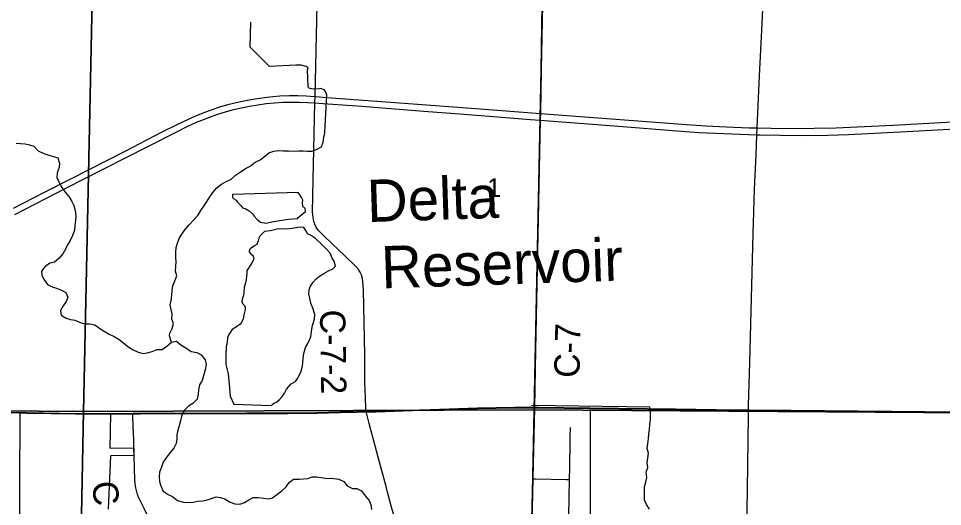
# Model space of a CAD drawing. Extents: x 0 to 42, y 0 to 22.
# Drawn here: x 5.107 to 7.178, y 18.271 to 19.367 of the extents above; entities that cross this region are included whole.
import ezdxf

# ---------------------------------------------------------------- set-up
doc = ezdxf.new("R2010")
doc.units = 0
for name, color, linetype in [('GM_X_City_Street', 7, 'Continuous'), ('GM_X_Corporation', 7, 'Continuous'), ('GM_X_County_Road', 7, 'Continuous'), ('GM_X_County_Road_Text', 7, 'Continuous'), ('GM_X_Interchange_Ramps', 7, 'Continuous'), ('GM_X_Interstate_Route', 7, 'Continuous'), ('GM_X_Minor_Lake', 7, 'Continuous'), ('GM_X_Minor_Lake_Text', 7, 'Continuous'), ('GM_X_Minor_River', 7, 'Continuous'), ('GM_X_Section', 7, 'Continuous'), ('GM_X_Section_Text', 7, 'Continuous')]:
    doc.layers.add(name, color=color, linetype=linetype)

msp = doc.modelspace()

# ---------------------------------------------------------------- linework, layer by layer
at = {"layer": 'GM_X_City_Street'}
for points in [[(6.3392, 18.1894), (6.3395, 18.2097), (6.342, 18.3322), (6.3425, 18.3585), (6.3435, 18.4175), (6.3436, 18.4268), (6.344, 18.4485)], [(6.2602, 18.3336), (6.266, 18.3335), (6.3355, 18.3324), (6.342, 18.3322)]]:
    msp.add_lwpolyline(points, dxfattribs=at)
at = {"layer": 'GM_X_Corporation'}
for points in [[(5.1081, 17.9802), (5.1104, 18.482), (5.3134, 18.4797), (5.3118, 18.4023), (5.365, 18.4029), (5.3657, 18.3857), (5.3129, 18.3855), (5.308, 18.2653)], [(6.2578, 18.2418), (6.26, 18.3342), (6.2632, 18.4934), (6.388, 18.4919), (6.3873, 17.9866)]]:
    msp.add_lwpolyline(points, dxfattribs=at)
at = {"layer": 'GM_X_County_Road'}
for p, q in [((5.3137, 18.4792), (5.3632, 18.4794)), ((6.2602, 18.3336), (6.2634, 18.4929)), ((5.3659, 18.3852), (5.3652, 18.4023)), ((6.2581, 18.2423), (6.2602, 18.3336))]:
    msp.add_line(p, q, dxfattribs=at)
for points in [[(6.2634, 18.4929), (6.266, 18.6228), (6.2765, 19.1383), (6.2768, 19.1534), (6.2825, 19.496), (6.2825, 19.5006)], [(6.7429, 18.4872), (6.7432, 18.4982), (6.7458, 18.5945), (6.7537, 18.8835), (6.7565, 18.983), (6.76, 19.0605), (6.762, 19.1054), (6.7628, 19.1211), (6.7681, 19.2375), (6.7728, 19.34), (6.7796, 19.4828), (6.7799, 19.4859), (6.7804, 19.4929)], [(5.8867, 18.4837), (5.8857, 18.491), (5.8849, 18.5158), (5.8835, 18.5499), (5.8834, 18.5622), (5.8829, 18.6119), (5.8799, 18.7577), (5.879, 18.7764), (5.8774, 18.7858), (5.8754, 18.7917), (5.8726, 18.7974), (5.8673, 18.8052), (5.8611, 18.8123), (5.8387, 18.834), (5.809, 18.8615), (5.791, 18.8785), (5.7803, 18.8897), (5.7749, 18.8971), (5.7708, 18.9053), (5.7688, 18.9111), (5.767, 18.9201), (5.7662, 18.9324), (5.7674, 19.0039), (5.7713, 19.1769), (5.7716, 19.1917), (5.7779, 19.4669)], [(4.9979, 18.4834), (5.0604, 18.4821), (5.1106, 18.4815)], [(5.1106, 18.4815), (5.1257, 18.4813), (5.2345, 18.4792), (5.2842, 18.479), (5.3137, 18.4792)], [(5.3632, 18.4794), (5.3806, 18.4795), (5.5359, 18.4799), (5.6167, 18.4801), (5.6571, 18.4802), (5.71, 18.4803), (5.7752, 18.4811), (5.828, 18.4823), (5.8653, 18.4832), (5.8867, 18.4837)], [(5.3652, 18.4023), (5.365, 18.422), (5.3645, 18.4344), (5.3634, 18.4717), (5.3632, 18.4794)], [(5.8867, 18.4837), (5.9088, 18.4841), (6.03, 18.4882), (6.1357, 18.4917), (6.2196, 18.4929), (6.2447, 18.4928), (6.2634, 18.4929)], [(5.9513, 18.2386), (5.9509, 18.2406), (5.9486, 18.2495), (5.943, 18.2701), (5.9341, 18.3034), (5.9307, 18.3166), (5.9161, 18.3708), (5.8927, 18.4578), (5.8869, 18.4819), (5.8867, 18.4837)], [(6.2634, 18.4929), (6.2722, 18.4927), (6.3883, 18.4914)], [(6.3883, 18.4914), (6.58, 18.4892), (6.7167, 18.4875), (6.7429, 18.4872)], [(6.7363, 17.9846), (6.7365, 17.9926), (6.737, 18.0454), (6.7383, 18.1199), (6.7389, 18.1758), (6.7408, 18.3094), (6.7431, 18.474), (6.7429, 18.4872)], [(6.7429, 18.4872), (6.838, 18.4861), (7.1395, 18.4831), (7.2576, 18.4819), (7.4161, 18.4806), (7.6026, 18.4793), (7.7538, 18.4779)], [(5.4086, 18.2289), (5.3993, 18.2459), (5.3924, 18.2592), (5.3886, 18.2673), (5.3785, 18.2865), (5.3758, 18.2922), (5.3736, 18.2981), (5.3719, 18.3042), (5.3699, 18.3133), (5.3685, 18.3226), (5.3679, 18.332), (5.3667, 18.3567), (5.3659, 18.3852)]]:
    msp.add_lwpolyline(points, dxfattribs=at)
at = {"layer": 'GM_X_Interchange_Ramps'}
for points in [[(6.2823, 19.4965), (6.2766, 19.154), (6.2763, 19.1388), (6.2658, 18.6234), (6.2632, 18.4934), (6.272, 18.4933), (6.388, 18.4919), (6.5797, 18.4897), (6.7165, 18.488), (6.7427, 18.4877), (6.8377, 18.4866), (7.1392, 18.4837), (7.2573, 18.4825), (7.4159, 18.4812), (7.6024, 18.4799), (7.7535, 18.4785), (7.7609, 18.4784), (8.0033, 18.4733), (8.2022, 18.4691), (8.2646, 18.468), (8.3265, 18.4669), (8.6747, 18.462), (8.9, 18.4589), (8.9, 20.9)], [(5.0602, 18.4826), (5.1104, 18.482), (5.1255, 18.4818), (5.2343, 18.4797), (5.284, 18.4796), (5.3134, 18.4797), (5.3629, 18.4799), (5.3803, 18.48), (5.5357, 18.4805), (5.6165, 18.4807), (5.6569, 18.4808), (5.7097, 18.4808), (5.775, 18.4817), (5.8278, 18.4829), (5.8651, 18.4838), (5.8865, 18.4842), (5.9086, 18.4846), (6.0298, 18.4887), (6.1354, 18.4922), (6.2194, 18.4934), (6.2445, 18.4934), (6.2632, 18.4934), (6.2658, 18.6234), (6.2763, 19.1388), (6.2766, 19.154), (6.2823, 19.4965)], [(6.2578, 18.2418), (6.26, 18.3342), (6.2632, 18.4934), (6.2445, 18.4934), (6.2194, 18.4934), (6.1354, 18.4922), (6.0298, 18.4887), (5.9086, 18.4846), (5.8865, 18.4842), (5.8651, 18.4838), (5.8278, 18.4829), (5.775, 18.4817), (5.7097, 18.4808), (5.6569, 18.4808), (5.6165, 18.4807), (5.5357, 18.4805), (5.3803, 18.48), (5.3629, 18.4799), (5.3134, 18.4797), (5.284, 18.4796), (5.2343, 18.4797), (5.1255, 18.4818), (5.1104, 18.482), (5.0602, 18.4826)], [(7.2573, 18.4825), (7.1392, 18.4837), (6.8377, 18.4866), (6.7427, 18.4877), (6.7165, 18.488), (6.5797, 18.4897), (6.388, 18.4919), (6.272, 18.4933), (6.2632, 18.4934), (6.26, 18.3342), (6.2578, 18.2418)]]:
    msp.add_lwpolyline(points, dxfattribs=at)
at = {"layer": 'GM_X_Interstate_Route'}
for points in [[(5.0957, 18.9409), (5.1648, 18.9765), (5.2258, 19.0074), (5.3475, 19.0699), (5.4277, 19.1111), (5.4611, 19.1278), (5.4891, 19.1412), (5.5061, 19.1488), (5.5233, 19.1559), (5.5408, 19.1624), (5.5585, 19.1682), (5.5764, 19.1734), (5.5944, 19.178), (5.6157, 19.1826), (5.6371, 19.1864), (5.6586, 19.1895), (5.6771, 19.1915), (5.6926, 19.1926), (5.7143, 19.1934), (5.7329, 19.1935), (5.7515, 19.193), (5.7701, 19.1918), (5.7716, 19.1917), (5.798, 19.1895), (5.9716, 19.1768), (6.1515, 19.163), (6.2476, 19.1556), (6.2768, 19.1534), (6.3561, 19.1476), (6.6041, 19.1285), (6.6475, 19.1257), (6.6941, 19.1233), (6.7439, 19.1215), (6.7628, 19.1211), (6.7936, 19.1204), (6.8589, 19.1199), (6.89, 19.1202), (6.9398, 19.1214), (6.9864, 19.1231), (7.0672, 19.1271), (7.2007, 19.1346)], [(5.0988, 18.9264), (5.2148, 18.9863), (5.345, 19.0528), (5.4557, 19.1094), (5.4864, 19.1246), (5.5062, 19.1337), (5.5234, 19.1409), (5.5408, 19.1476), (5.5556, 19.1526), (5.5705, 19.1572), (5.5885, 19.162), (5.6067, 19.1663), (5.625, 19.17), (5.6435, 19.1731), (5.662, 19.1755), (5.6806, 19.1773), (5.6993, 19.1784), (5.7179, 19.1788), (5.7366, 19.1786), (5.7553, 19.1779), (5.7713, 19.1769), (5.7894, 19.1757), (5.8763, 19.1694), (6.0157, 19.1583), (6.1057, 19.1516), (6.2266, 19.1421), (6.2545, 19.14), (6.2765, 19.1383), (6.4613, 19.124), (6.573, 19.1154), (6.6321, 19.111), (6.762, 19.1054), (6.7691, 19.1051), (6.8151, 19.1048), (6.8619, 19.1039), (6.921, 19.1049), (6.9676, 19.1063), (7.098, 19.1128), (7.2346, 19.1201)]]:
    msp.add_lwpolyline(points, dxfattribs=at)
at = {"layer": 'GM_X_Minor_Lake'}
for p, q in [((5.7341, 18.9763), (5.5868, 18.9716)), ((5.5897, 18.5013), (5.6731, 18.4982))]:
    msp.add_line(p, q, dxfattribs=at)
for points in [[(5.5868, 18.9716), (5.5862, 18.9648), (5.5896, 18.9617), (5.5944, 18.9589), (5.5981, 18.9543), (5.6014, 18.9508), (5.6051, 18.9466), (5.6088, 18.9419), (5.6152, 18.9399), (5.6242, 18.9351), (5.6309, 18.9289), (5.6353, 18.9231), (5.6416, 18.9154), (5.6494, 18.9095), (5.6615, 18.9073), (5.6787, 18.9111), (5.7118, 18.9165), (5.7319, 18.9179), (5.7335, 18.9198), (5.7416, 18.9268), (5.7501, 18.9338), (5.7492, 18.9407), (5.7439, 18.9442), (5.7434, 18.9533), (5.7443, 18.9586), (5.7414, 18.9648), (5.7377, 18.9705), (5.7341, 18.9763)], [(5.6731, 18.4982), (5.6781, 18.5023), (5.6858, 18.5063), (5.692, 18.5119), (5.6982, 18.5182), (5.703, 18.5257), (5.7073, 18.5347), (5.7179, 18.5466), (5.7275, 18.5517), (5.7326, 18.5584), (5.7397, 18.5731), (5.7435, 18.5866), (5.745, 18.6037), (5.7464, 18.6147), (5.7498, 18.6283), (5.7553, 18.6369), (5.7621, 18.6519), (5.7635, 18.6648), (5.7661, 18.6776), (5.7702, 18.6916), (5.7709, 18.7022), (5.7666, 18.7163), (5.762, 18.7278), (5.7596, 18.7389), (5.7575, 18.748), (5.7585, 18.7583), (5.7614, 18.7662), (5.7676, 18.7751), (5.7739, 18.7822), (5.7812, 18.7885), (5.7916, 18.794), (5.802, 18.8006), (5.8116, 18.8045), (5.8171, 18.8109), (5.8147, 18.8219), (5.8103, 18.8285), (5.8052, 18.8396), (5.7956, 18.8504), (5.7871, 18.8597), (5.7726, 18.873), (5.761, 18.8801), (5.755, 18.8832), (5.7521, 18.8886), (5.7466, 18.8975), (5.7406, 18.8983), (5.733, 18.8974), (5.72, 18.895), (5.7079, 18.8941), (5.69, 18.8942), (5.6717, 18.8904), (5.658, 18.8884), (5.6537, 18.8843), (5.6479, 18.878), (5.6452, 18.8739), (5.6443, 18.8679), (5.6426, 18.8637), (5.6414, 18.8592), (5.636, 18.8563), (5.6264, 18.8497), (5.6232, 18.844), (5.628, 18.8386), (5.6332, 18.8339), (5.6345, 18.8263), (5.6302, 18.8181), (5.6227, 18.8065), (5.6188, 18.8012), (5.6183, 18.7956), (5.6177, 18.7876), (5.6175, 18.7804), (5.6155, 18.7736), (5.6129, 18.7627), (5.6123, 18.7509), (5.611, 18.746), (5.6082, 18.7369), (5.6073, 18.7317), (5.609, 18.7267), (5.6135, 18.7228), (5.6149, 18.7178), (5.6148, 18.7136), (5.6123, 18.7016), (5.611, 18.6966), (5.6101, 18.6917), (5.6058, 18.6835), (5.6034, 18.6805), (5.5957, 18.6746), (5.5857, 18.6687), (5.5813, 18.662), (5.5782, 18.6571), (5.5754, 18.65), (5.5744, 18.6413), (5.5722, 18.6299), (5.5715, 18.6125), (5.5717, 18.5905), (5.5769, 18.5691), (5.579, 18.5451), (5.581, 18.5189), (5.5897, 18.5013)]]:
    msp.add_lwpolyline(points, dxfattribs=at)
at = {"layer": 'GM_X_Minor_River'}
msp.add_line((6.5219, 18.4944), (6.2568, 18.4982), dxfattribs=at)
for points in [[(5.7934, 19.1113), (5.7977, 19.1943), (5.7952, 19.2027), (5.7922, 19.2062), (5.784, 19.2094), (5.7811, 19.2089), (5.768, 19.2082), (5.7605, 19.2096), (5.7571, 19.2108), (5.756, 19.2138), (5.755, 19.2514), (5.7558, 19.2556), (5.7514, 19.2587), (5.7408, 19.2616), (5.7287, 19.2619), (5.6698, 19.259), (5.6264, 19.3025), (5.6274, 19.3579)], [(5.4499, 18.6403), (5.4451, 18.6544), (5.4459, 18.6605), (5.451, 18.6706), (5.454, 18.6819), (5.4508, 18.6915), (5.4514, 18.7036), (5.4494, 18.7135), (5.4466, 18.7231), (5.4491, 18.7337), (5.4509, 18.745), (5.4511, 18.756), (5.4529, 18.767), (5.4573, 18.7775), (5.4614, 18.7888), (5.459, 18.7995), (5.4592, 18.8097), (5.4599, 18.8207), (5.4597, 18.8302), (5.4596, 18.8412), (5.4603, 18.8526), (5.4635, 18.8624), (5.4668, 18.8726), (5.4727, 18.8827), (5.4802, 18.8928), (5.4892, 18.9036), (5.4985, 18.9136), (5.5086, 18.9244), (5.5153, 18.9357), (5.522, 18.9454), (5.5299, 18.9566), (5.5354, 18.9663), (5.5425, 18.9764), (5.5514, 18.9865), (5.5619, 18.995), (5.5723, 19.0004), (5.583, 19.0055), (5.5931, 19.0148), (5.6039, 19.0217), (5.6154, 19.0298), (5.6262, 19.0353), (5.637, 19.0442), (5.6482, 19.0492), (5.6582, 19.0566), (5.6683, 19.0647), (5.6793, 19.0686), (5.6896, 19.0703), (5.7002, 19.0693), (5.7124, 19.0698), (5.723, 19.0688), (5.7351, 19.0697), (5.7446, 19.0698), (5.7545, 19.0689), (5.7647, 19.0686), (5.7751, 19.0726), (5.7858, 19.0788), (5.7895, 19.089), (5.7913, 19.0999), (5.7934, 19.1097), (5.7934, 19.1113)], [(5.1016, 19.0869), (5.1114, 19.0863), (5.1216, 19.0849), (5.1314, 19.0828), (5.1412, 19.0799), (5.1512, 19.0698), (5.1636, 19.0635), (5.1745, 19.0598), (5.1851, 19.0569), (5.1952, 19.054), (5.1991, 19.0422), (5.1978, 19.032), (5.1937, 19.0199), (5.1927, 19.0097), (5.1977, 18.9982), (5.2043, 18.9874), (5.2113, 18.977), (5.2194, 18.9669), (5.2263, 18.9562), (5.2307, 18.9466), (5.2338, 18.9359), (5.2351, 18.9248), (5.2348, 18.9131), (5.2334, 18.9021), (5.232, 18.8907), (5.2276, 18.8798), (5.2224, 18.8682), (5.2164, 18.8584), (5.2124, 18.8487), (5.2061, 18.8386), (5.1971, 18.8281), (5.1874, 18.8196), (5.1768, 18.8172), (5.1659, 18.8091), (5.1581, 18.7994), (5.159, 18.7895), (5.1641, 18.7799), (5.1718, 18.7699), (5.182, 18.7647), (5.1921, 18.7611), (5.203, 18.757), (5.2128, 18.7519), (5.2171, 18.7411), (5.2134, 18.7313), (5.2071, 18.7216), (5.2008, 18.7115), (5.2028, 18.7005), (5.2137, 18.6941), (5.2235, 18.6913), (5.2337, 18.6895), (5.2453, 18.6847), (5.2555, 18.6814), (5.2669, 18.6812), (5.2782, 18.679), (5.289, 18.6708), (5.2991, 18.6653), (5.3089, 18.659), (5.3212, 18.653), (5.3325, 18.6459), (5.3541, 18.6288), (5.3642, 18.6228), (5.3754, 18.618), (5.386, 18.6151), (5.3955, 18.6161), (5.4066, 18.6192), (5.4177, 18.6235), (5.4287, 18.624), (5.4391, 18.631), (5.4499, 18.6403), (5.461, 18.6427), (5.471, 18.6345), (5.4838, 18.6262), (5.4942, 18.6195), (5.5063, 18.6174), (5.5164, 18.6115), (5.5249, 18.6003)], [(5.5249, 18.6003), (5.5273, 18.59), (5.5255, 18.5782), (5.5214, 18.5647), (5.5189, 18.5545), (5.5122, 18.5447), (5.5104, 18.5334), (5.5094, 18.5235), (5.5076, 18.5126), (5.4975, 18.5029), (5.4879, 18.4967), (5.4782, 18.487), (5.4722, 18.4739), (5.4697, 18.4637), (5.4671, 18.4527), (5.4639, 18.443), (5.4621, 18.4327), (5.4615, 18.4229), (5.4601, 18.413), (5.4553, 18.4025), (5.4463, 18.3917), (5.4377, 18.3809), (5.4314, 18.3708), (5.4274, 18.3599), (5.4229, 18.3486), (5.422, 18.3384), (5.4232, 18.3277), (5.4256, 18.3178), (5.4311, 18.3063), (5.4423, 18.2984), (5.4524, 18.294), (5.4632, 18.2847), (5.4764, 18.281), (5.4858, 18.2808), (5.4984, 18.2816), (5.5079, 18.2833), (5.5201, 18.2842), (5.53, 18.2866), (5.5396, 18.2894), (5.5499, 18.2934), (5.5597, 18.292), (5.5695, 18.2888), (5.5815, 18.2809), (5.5916, 18.2773), (5.603, 18.2766), (5.6133, 18.2806), (5.6233, 18.2868), (5.6329, 18.2919), (5.6443, 18.2916), (5.6564, 18.2906), (5.6663, 18.2889), (5.6762, 18.2913), (5.6858, 18.2987), (5.6974, 18.3064), (5.7071, 18.3157), (5.7134, 18.3254), (5.7231, 18.3328), (5.7356, 18.3332), (5.7455, 18.3334), (5.7557, 18.3343), (5.7653, 18.3383), (5.7748, 18.3381), (5.7858, 18.3367), (5.7979, 18.3345), (5.8081, 18.3354), (5.8251, 18.3331), (5.836, 18.3276), (5.8437, 18.3179), (5.8554, 18.3123), (5.8656, 18.3117), (5.8754, 18.3066), (5.8842, 18.2958), (5.8931, 18.2853), (5.8966, 18.2754), (5.8979, 18.2647)], [(6.5214, 18.2654), (6.5145, 18.2758), (6.5097, 18.2858), (6.5101, 18.3063), (6.51, 18.3158), (6.5128, 18.326), (6.5153, 18.3366), (6.514, 18.3488), (6.5173, 18.3593), (6.516, 18.3692), (6.5177, 18.3802), (6.5187, 18.3912), (6.5162, 18.4015), (6.5176, 18.4125), (6.5193, 18.4238), (6.5195, 18.4341), (6.5209, 18.4443), (6.5223, 18.4564), (6.5232, 18.4663), (6.5237, 18.4883), (6.5219, 18.4944)]]:
    msp.add_lwpolyline(points, dxfattribs=at)
at = {"layer": 'GM_X_Section'}
for points in [[(5.2524, 18.4847), (4.2501, 18.4923), (4.2741, 19.5242), (5.2739, 19.514)], [(5.2809, 19.5139), (6.2834, 19.5071), (6.2631, 18.4885), (5.2524, 18.4847), (5.2739, 19.514)], [(6.2834, 19.5071), (7.2774, 19.4824), (7.2453, 18.4817), (6.2631, 18.4885)], [(4.2501, 18.4923), (5.2524, 18.4847), (5.2334, 17.4797), (4.2338, 17.4876)], [(5.2524, 18.4847), (6.2631, 18.4885), (6.2427, 17.4846), (5.2334, 17.4797)], [(6.2631, 18.4885), (7.2453, 18.4817), (7.2316, 17.475), (6.2427, 17.4846)]]:
    msp.add_lwpolyline(points, close=True, dxfattribs=at)

# ---------------------------------------------------------------- texts
at = {"layer": 'GM_X_County_Road_Text'}
for s, height, rotation, p in [('C-7-2', 0.05682, 270.8839, (5.7825, 18.7129)), ('C-7', 0.05682, 88.6291, (6.3641, 18.5597)), ('C', 0.0568, 277.1807, (5.2709, 18.3251))]:
    msp.add_text(s, height=height, rotation=rotation, dxfattribs=at).set_placement(p)
at = {"layer": 'GM_X_Minor_Lake_Text'}
for s, rotation, p in [('Delta', 1.8965, (5.8892, 18.9096)), ('Reservoir', 1.8967, (5.9212, 18.7608))]:
    msp.add_text(s, height=0.09476, rotation=rotation, dxfattribs=at).set_placement(p)
at = {"layer": 'GM_X_Section_Text'}
msp.add_text('1', height=0.0419, rotation=0, dxfattribs=at).set_placement((6.1574, 18.9662))

doc.saveas('drawing.dxf')
